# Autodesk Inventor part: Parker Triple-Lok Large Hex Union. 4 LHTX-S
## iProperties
Shininess: 20.0
Length Units: 11272
Angle Units: 11279
Time Units: 11290
Mass Units: 11286
Length Display Precision: 3
Angle Display Precision: 2
Created: 2001-09
Part Number: Parker Triple-Lok Large Hex Union. 4 LHTX-S
Material: Stainless Steel, Austenitic
Description: Parker Triple-Lok Large Hex Union. 4 LHTX-S
Document SubType Name: Modeling
Designer: jhagarty
Density: 0.0
Volumn: 0.0
Area: 0.0
PropertySet Name: Model Information
Control State: 0
Master: False
Checked Out: False
Last Check In By: Charles Bliss
Last Check In Date: 2003-09-27
Author: jhagarty
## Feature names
1. Extrusion1
2. Revolution3
3. Mirror2
4. Revolution1
5. Hole3
6. Revolution6
7. Hole4
